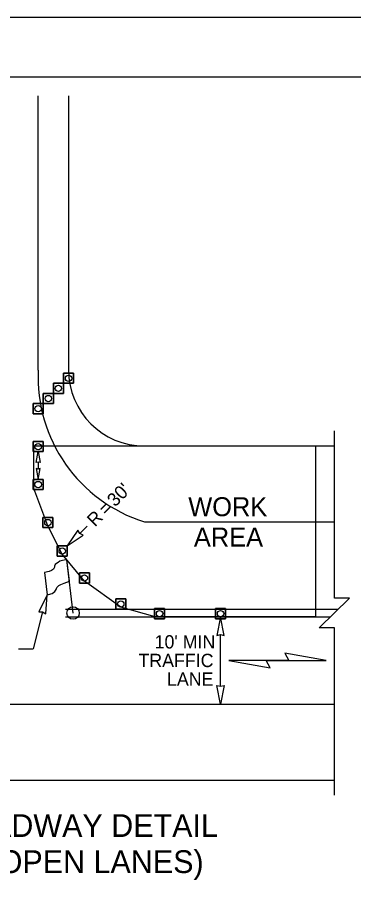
# Model space of a CAD drawing. Extents: x 99998.9 to 100095.7, y 99995 to 100010.7.
# Drawn here: x 100028.607 to 100030.375, y 100006.062 to 100010.687 of the extents above; entities that cross this region are included whole.
import ezdxf

# ---------------------------------------------------------------- set-up
doc = ezdxf.new("R2010")
doc.units = 0
for name, color, linetype in [('RD_ED_ShoulderPavedEdge', 7, 'Continuous'), ('RD_MK_LineDblYellowCenter', 7, 'Continuous'), ('RD_MK_LineEdgeWhite', 7, 'Continuous'), ('SH_DE_DetailHeading2Text', 7, 'Continuous'), ('SH_GI_PlotLimits', 7, 'Continuous'), ('SH_GI_SheetBorder', 7, 'Continuous'), ('TR_WZ_FlaggingStation', 7, 'Continuous'), ('TR_WZ_TrafficCone', 7, 'Continuous'), ('TR_WZ_WorkAreaLabel', 7, 'Continuous'), ('TR_WZ_WorkZoneDetails', 7, 'Continuous'), ('TR_WZ_WorkZoneTextCurrent', 7, 'Continuous')]:
    doc.layers.add(name, color=color, linetype=linetype)

msp = doc.modelspace()

# ---------------------------------------------------------------- linework, layer by layer
at = {"layer": 'RD_ED_ShoulderPavedEdge'}
for p, q in [((100029.275, 100008.4305), (100030.275, 100008.4305)), ((100025.475, 100006.6704), (100030.275, 100006.6704))]:
    msp.add_line(p, q, dxfattribs=at)
msp.add_lwpolyline([(100028.875, 100010.275), (100028.875, 100008.8304)], dxfattribs=at)
msp.add_arc((100029.275, 100008.8304), 0.4, 180, 270, dxfattribs=at)
at = {"layer": 'RD_MK_LineDblYellowCenter'}
for p, q in [((100028.8588, 100007.5704), (100030.2957, 100007.5704)), ((100028.8588, 100007.5305), (100030.2543, 100007.5305))]:
    msp.add_line(p, q, dxfattribs=at)
at = {"layer": 'RD_MK_LineEdgeWhite'}
for p, q in [((100028.715, 100008.8304), (100028.715, 100010.275)), ((100029.275, 100008.0305), (100030.275, 100008.0305)), ((100025.475, 100007.0704), (100030.275, 100007.0704))]:
    msp.add_line(p, q, dxfattribs=at)
msp.add_arc((100029.5142, 100008.7939), 0.8, 177.3788, 252.6052, dxfattribs=at)
at = {"layer": 'SH_GI_PlotLimits'}
msp.add_lwpolyline([(100019.0625, 99999.6875), (100036.0625, 99999.6875), (100036.0625, 100010.6875), (100019.0625, 100010.6875)], close=True, dxfattribs=at)
at = {"layer": 'SH_GI_SheetBorder'}
msp.add_line((100020, 100010.375), (100035.75, 100010.375), dxfattribs=at)
at = {"layer": 'TR_WZ_FlaggingStation'}
for p, q in [((100028.8797, 100007.7174), (100028.8667, 100007.8317)), ((100028.8988, 100007.5504), (100028.8667, 100007.8314)), ((100028.7487, 100007.7639), (100028.762, 100007.6467)), ((100028.8797, 100007.7174), (100028.8797, 100007.7174))]:
    msp.add_line(p, q, dxfattribs=at)
for points in [[(100028.8667, 100007.8317), (100028.8609, 100007.8304), (100028.8431, 100007.827), (100028.8293, 100007.8228), (100028.8196, 100007.8167), (100028.8111, 100007.812), (100028.8054, 100007.8052), (100028.8012, 100007.7973), (100028.8006, 100007.7912), (100028.7953, 100007.7819), (100028.7845, 100007.7745), (100028.7721, 100007.7693), (100028.7487, 100007.7639)], [(100028.762, 100007.6467), (100028.7702, 100007.6481), (100028.7879, 100007.6528), (100028.8035, 100007.6633), (100028.81, 100007.6738), (100028.814, 100007.6841), (100028.823, 100007.695), (100028.834, 100007.7012), (100028.8514, 100007.7083), (100028.8797, 100007.7174)]]:
    msp.add_lwpolyline(points, dxfattribs=at)
msp.add_circle((100028.8988, 100007.5504), 0.0325, dxfattribs=at)
at = {"layer": 'TR_WZ_TrafficCone'}
for points in [[(100028.8483, 100008.8138), (100028.9016, 100008.8138), (100028.9016, 100008.7605), (100028.8483, 100008.7605), (100028.8483, 100008.8138)], [(100028.8483, 100008.7605), (100028.9016, 100008.7605), (100028.9016, 100008.8138), (100028.8483, 100008.8138), (100028.8483, 100008.7605)], [(100028.795, 100008.7605), (100028.8483, 100008.7605), (100028.8483, 100008.7071), (100028.795, 100008.7071), (100028.795, 100008.7605)], [(100028.795, 100008.7071), (100028.8483, 100008.7071), (100028.8483, 100008.7605), (100028.795, 100008.7605), (100028.795, 100008.7071)], [(100028.7416, 100008.7071), (100028.795, 100008.7071), (100028.795, 100008.6538), (100028.7416, 100008.6538), (100028.7416, 100008.7071)], [(100028.7416, 100008.6538), (100028.795, 100008.6538), (100028.795, 100008.7071), (100028.7416, 100008.7071), (100028.7416, 100008.6538)], [(100028.6883, 100008.6538), (100028.7416, 100008.6538), (100028.7416, 100008.6005), (100028.6883, 100008.6005), (100028.6883, 100008.6538)], [(100028.6883, 100008.6005), (100028.7416, 100008.6005), (100028.7416, 100008.6538), (100028.6883, 100008.6538), (100028.6883, 100008.6005)], [(100028.6883, 100008.4538), (100028.7416, 100008.4538), (100028.7416, 100008.4005), (100028.6883, 100008.4005), (100028.6883, 100008.4538)], [(100028.6883, 100008.4005), (100028.7416, 100008.4005), (100028.7416, 100008.4538), (100028.6883, 100008.4538), (100028.6883, 100008.4005)], [(100028.6883, 100008.2538), (100028.7416, 100008.2538), (100028.7416, 100008.2005), (100028.6883, 100008.2005), (100028.6883, 100008.2538)], [(100028.6883, 100008.2005), (100028.7416, 100008.2005), (100028.7416, 100008.2538), (100028.6883, 100008.2538), (100028.6883, 100008.2005)], [(100028.7393, 100008.0538), (100028.7927, 100008.0538), (100028.7927, 100008.0005), (100028.7393, 100008.0005), (100028.7393, 100008.0538)], [(100028.7393, 100008.0005), (100028.7927, 100008.0005), (100028.7927, 100008.0538), (100028.7393, 100008.0538), (100028.7393, 100008.0005)], [(100028.815, 100007.9038), (100028.8683, 100007.9038), (100028.8683, 100007.8505), (100028.815, 100007.8505), (100028.815, 100007.9038)], [(100028.815, 100007.8505), (100028.8683, 100007.8505), (100028.8683, 100007.9038), (100028.815, 100007.9038), (100028.815, 100007.8505)], [(100028.9319, 100007.7615), (100028.9853, 100007.7615), (100028.9853, 100007.7082), (100028.9319, 100007.7082), (100028.9319, 100007.7615)], [(100028.9319, 100007.7082), (100028.9853, 100007.7082), (100028.9853, 100007.7615), (100028.9319, 100007.7615), (100028.9319, 100007.7082)], [(100029.1236, 100007.6247), (100029.177, 100007.6247), (100029.177, 100007.5714), (100029.1236, 100007.5714), (100029.1236, 100007.6247)], [(100029.1236, 100007.5714), (100029.177, 100007.5714), (100029.177, 100007.6247), (100029.1236, 100007.6247), (100029.1236, 100007.5714)], [(100029.3276, 100007.5738), (100029.381, 100007.5738), (100029.381, 100007.5205), (100029.3276, 100007.5205), (100029.3276, 100007.5738)], [(100029.3276, 100007.5205), (100029.381, 100007.5205), (100029.381, 100007.5738), (100029.3276, 100007.5738), (100029.3276, 100007.5205)], [(100029.649, 100007.5738), (100029.7024, 100007.5738), (100029.7024, 100007.5205), (100029.649, 100007.5205), (100029.649, 100007.5738)], [(100029.649, 100007.5205), (100029.7024, 100007.5205), (100029.7024, 100007.5738), (100029.649, 100007.5738), (100029.649, 100007.5205)]]:
    msp.add_lwpolyline(points, dxfattribs=at)
for centre in [(100028.875, 100008.7871), (100028.8216, 100008.7338), (100028.7683, 100008.6805), (100028.715, 100008.6271), (100028.715, 100008.4271), (100028.715, 100008.2271), (100028.766, 100008.0271), (100028.8417, 100007.8771), (100028.9586, 100007.7349), (100029.1503, 100007.598), (100029.3543, 100007.5471), (100029.6757, 100007.5471)]:
    msp.add_circle(centre, 0.0167, dxfattribs=at)
at = {"layer": 'TR_WZ_WorkZoneDetails'}
for p, q in [((100028.715, 100008.3459), (100028.715, 100008.3083)), ((100028.9346, 100007.9701), (100028.973, 100008.0085)), ((100028.7385, 100007.556), (100028.688, 100007.3613)), ((100029.6756, 100007.1642), (100029.6756, 100007.4367)), ((100028.6118, 100007.3613), (100028.688, 100007.3613)), ((100030.0356, 100007.3005), (100029.7945, 100007.3005)), ((100029.9151, 100007.3005), (100030.1562, 100007.3005))]:
    msp.add_line(p, q, dxfattribs=at)
msp.add_lwpolyline([(100030.275, 100006.5904), (100030.275, 100007.473), (100030.195, 100007.473), (100030.355, 100007.6279), (100030.275, 100007.6279), (100030.275, 100008.5105)], dxfattribs=at)
for points in [[(100030.175, 100008.4305), (100030.175, 100007.5305), (100029.699, 100007.5305), (100029.6523, 100007.5305), (100029.6523, 100007.5305), (100029.6523, 100007.5305), (100029.331, 100007.5305), (100029.331, 100007.5305), (100029.331, 100007.5305), (100029.1503, 100007.5814), (100028.9586, 100007.7182), (100028.8417, 100007.8605), (100028.766, 100008.0105), (100028.6917, 100008.2071), (100028.6917, 100008.4305)], [(100028.715, 100008.4005), (100028.7262, 100008.3433), (100028.715, 100008.3459), (100028.7037, 100008.3433)], [(100028.715, 100008.2538), (100028.7262, 100008.3109), (100028.715, 100008.3083), (100028.7038, 100008.3109)], [(100028.8683, 100007.9038), (100028.9514, 100007.9597), (100028.9346, 100007.9701), (100028.9242, 100007.987)], [(100028.762, 100007.6467), (100028.7187, 100007.5564), (100028.7385, 100007.556), (100028.7561, 100007.5467)], [(100029.6757, 100007.5305), (100029.6564, 100007.4322), (100029.6757, 100007.4367), (100029.695, 100007.4322)], [(100030.2321, 100007.3005), (100030.0133, 100007.339), (100030.0356, 100007.3005)], [(100029.7185, 100007.3005), (100029.9373, 100007.2619), (100029.9151, 100007.3005)], [(100029.6756, 100007.0704), (100029.6564, 100007.1687), (100029.6756, 100007.1642), (100029.6949, 100007.1687)]]:
    msp.add_lwpolyline(points, close=True, dxfattribs=at)

# ---------------------------------------------------------------- texts
at = {"layer": 'SH_DE_DetailHeading2Text'}
for s, p in [('UNSIGNALIZED INTERSECTING ROADWAY DETAIL', (100025.7563, 100006.3705)), ('SAME SIDE AS LANE CLOSURE (TWO OPEN LANES)', (100025.5738, 100006.1804))]:
    msp.add_text(s, height=0.12, rotation=360, dxfattribs=at).set_placement(p)
at = {"layer": 'TR_WZ_WorkAreaLabel'}
for s, p in [('WORK', (100029.5056, 100008.0605)), ('AREA', (100029.5352, 100007.9004))]:
    msp.add_text(s, height=0.1, dxfattribs=at).set_placement(p)
at = {"layer": 'TR_WZ_WorkZoneTextCurrent'}
for s, p in [("30'", (100029.1202, 100008.1062)), ('=', (100029.0734, 100008.0593)), ('R', (100029.0142, 100008.0002))]:
    msp.add_text(s, height=0.07, rotation=45, dxfattribs=at).set_placement(p)
for s, p in [("10' MIN", (100029.3283, 100007.3635)), ('TRAFFIC', (100029.2433, 100007.2655)), ('LANE', (100029.3937, 100007.1675))]:
    msp.add_text(s, height=0.07, dxfattribs=at).set_placement(p)

doc.saveas('drawing.dxf')
